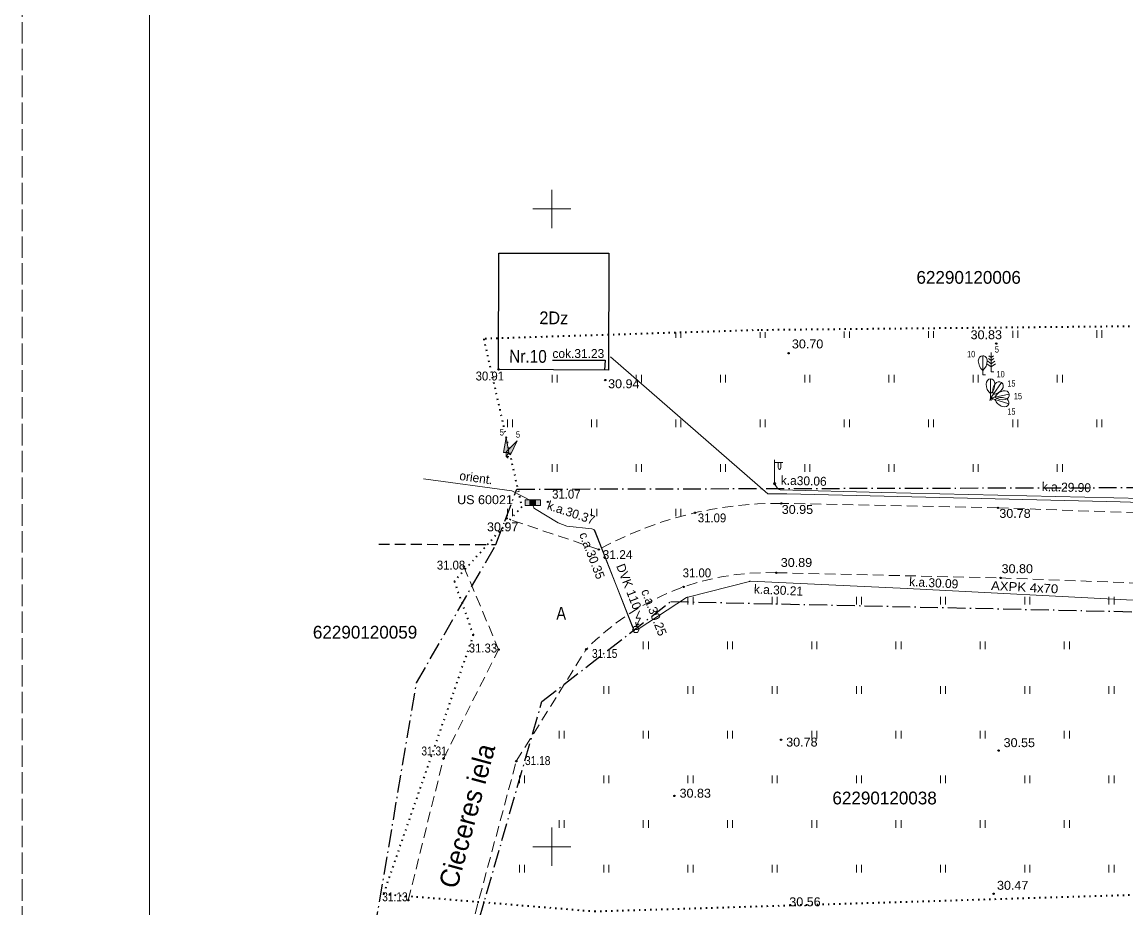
# Model space of a CAD drawing. Extents: x 380758 to 381729, y 283236 to 283533.
# Drawn here: x 380758.5 to 380845, y 283295.2 to 283364.6 of the extents above; entities that cross this region are included whole.
import ezdxf
from ezdxf.enums import TextEntityAlignment as Align

# ---------------------------------------------------------------- set-up
doc = ezdxf.new("R2010")
doc.units = 0
doc.header["$LTSCALE"] = 0.28
for name, pattern in [('DOT_DASHED', [7.7, 5, -1.2, 0.3, -1.2]), ('DOTTED', [1.5, 0.3, -1.2]), ('LONG_DASHED', [7.5, 6, -1.5]), ('MEDIUM_DASHED', [4.5, 3, -1.5])]:
    doc.linetypes.add(name, pattern=pattern)
for name, color, linetype, lineweight in [('1', 7, 'Continuous', 13), ('12', 7, 'Continuous', 13), ('17', 7, 'Continuous', 13), ('18', 7, 'Continuous', 13), ('23', 7, 'Continuous', 13), ('25', 7, 'DOTTED', 35), ('29', 7, 'DOT_DASHED', 25), ('30', 7, 'Continuous', 13), ('37', 7, 'MEDIUM_DASHED', 13), ('4', 7, 'Continuous', 13), ('40', 7, 'Continuous', 25), ('42', 7, 'Continuous', 13), ('44', 7, 'Continuous', 13), ('45', 7, 'Continuous', 13), ('58', 7, 'Continuous', 25), ('63', 7, 'Continuous', 13), ('7', 7, 'Continuous', 13)]:
    doc.layers.add(name, color=color, linetype=linetype, lineweight=lineweight)
for name, color, linetype in [('5', 7, 'Continuous'), ('56', 7, 'Continuous'), ('59', 7, 'Continuous')]:
    doc.layers.add(name, color=color, linetype=linetype)

msp = doc.modelspace()

# ---------------------------------------------------------------- hatches: boundary and pattern name
at = {"layer": '1'}
for points in [[(380796.204, 283330.898), (380796.624, 283330.898), (380796.414, 283332.078)], [(380796.424, 283330.961), (380796.769, 283330.721), (380797.271, 283331.809)]]:
    msp.add_hatch(color=256, dxfattribs=at).paths.add_polyline_path(points)
at = {"layer": '18'}
for points in [[(380797.9, 283327.193), (380799.1, 283327.193), (380799.1, 283326.743), (380797.9, 283326.743)], [(380798.724, 283326.748), (380798.276, 283326.748), (380798.276, 283327.188), (380798.724, 283327.188)]]:
    msp.add_hatch(color=256, dxfattribs=at).paths.add_polyline_path(points)

# ---------------------------------------------------------------- linework, layer by layer
at = {"layer": '1'}
for p, q in [((380834.439, 283338.739), (380834.439, 283337.239)), ((380833.778, 283338.491), (380833.778, 283337.343)), ((380834.439, 283337.613), (380834.107, 283337.857)), ((380834.439, 283337.863), (380834.161, 283338.067)), ((380834.439, 283338.113), (380834.223, 283338.271)), ((380834.439, 283338.363), (380834.263, 283338.491)), ((380834.439, 283338.363), (380834.613, 283338.491)), ((380834.439, 283338.113), (380834.655, 283338.271)), ((380834.439, 283337.863), (380834.717, 283338.067)), ((380834.439, 283337.613), (380834.773, 283337.857)), ((380833.778, 283337.343), (380833.778, 283336.991)), ((380833.778, 283336.991), (380833.978, 283336.991)), ((380834.439, 283337.239), (380834.639, 283337.239)), ((380834.384, 283336.671), (380834.384, 283335.523)), ((380835.251, 283336.395), (380834.587, 283335.458)), ((380834.384, 283335.523), (380834.384, 283335.171)), ((380834.587, 283335.458), (380834.384, 283335.171)), ((380834.728, 283335.245), (380834.384, 283335.171)), ((380835.851, 283335.485), (380834.728, 283335.245)), ((380834.384, 283335.171), (380834.324, 283334.98)), ((380834.384, 283335.171), (380834.584, 283335.171)), ((380834.384, 283335.171), (380834.547, 283335.055)), ((380834.384, 283335.171), (380834.426, 283334.975)), ((380834.72, 283335.065), (380834.384, 283335.171)), ((380835.815, 283334.72), (380834.72, 283335.065)), ((380796.414, 283330.578), (380796.414, 283330.898)), ((380796.414, 283330.578), (380796.597, 283330.841)), ((380796.414, 283330.578), (380796.624, 283330.578)), ((380796.414, 283330.578), (380796.586, 283330.458))]:
    msp.add_line(p, q, dxfattribs=at)
for points in [[(380796.204, 283330.898), (380796.624, 283330.898), (380796.414, 283332.078)], [(380796.424, 283330.961), (380796.769, 283330.721), (380797.271, 283331.809)]]:
    msp.add_lwpolyline(points, close=True, dxfattribs=at)
for centre, major_axis, start_param, end_param in [((380833.778, 283338.091), (0, 0.4), 0, 1.5707963), ((380834.2533, 283338.1144), (0, -0.9434), 4.7372004, 5.6697113), ((380833.778, 283338.091), (0, -0.4), 1.5707963, 3.1415927), ((380833.778, 283338.091), (0, -0.4), 1.5707963, 3.1415927), ((380833.3027, 283338.1144), (0, -0.9434), 0.613474, 1.5459849), ((380834.384, 283336.271), (0, 0.4), 0, 1.5707963), ((380834.8593, 283336.2944), (0, -0.9434), 4.7372004, 5.6697113), ((380834.384, 283336.271), (0, -0.4), 1.5707963, 3.1415927), ((380834.384, 283336.271), (0, -0.4), 1.5707963, 3.1415927), ((380833.9087, 283336.2944), (0, -0.9434), 0.613474, 1.5459849), ((380835.4211, 283335.8132), (-0.5452, -0.77), 4.7372004, 5.6697113), ((380835.0197, 283336.0687), (0.2312, 0.3264), 0, 1.5707963), ((380835.0197, 283336.0687), (0.2312, 0.3264), 4.712389, 6.2831853), ((380835.0197, 283336.0687), (0.2312, 0.3264), 4.712389, 6.2831853), ((380834.6453, 283336.3625), (-0.5452, -0.77), 0.613474, 1.5459849), ((380835.3127, 283334.3802), (-0.8998, 0.2835), 4.7372004, 5.6697113), ((380835.3832, 283335.8707), (-0.9226, -0.1973), 0.613474, 1.5459849), ((380835.582, 283334.9412), (-0.9226, -0.1973), 4.7372004, 5.6697113), ((380835.4597, 283335.401), (0.3912, 0.0836), 0, 1.5707963), ((380835.4597, 283335.401), (0.3912, 0.0836), 4.712389, 6.2831853), ((380835.4597, 283335.401), (0.3912, 0.0836), 4.712389, 6.2831853), ((380835.5983, 283335.2868), (-0.8998, 0.2835), 0.613474, 1.5459849), ((380835.4332, 283334.8405), (0.3815, -0.1202), 4.712389, 6.2831853), ((380835.4332, 283334.8405), (0.3815, -0.1202), 4.712389, 6.2831853), ((380835.4332, 283334.8405), (0.3815, -0.1202), 0, 1.5707963)]:
    msp.add_ellipse(centre, major_axis=major_axis, ratio=0.875, start_param=start_param, end_param=end_param, dxfattribs=at)
at = {"layer": '12'}
msp.add_line((380806.611, 283317.324), (380806.852, 283317.463), dxfattribs=at)
msp.add_lwpolyline([(380806.86, 283318.486), (380806.611, 283317.923), (380806.947, 283317.923), (380806.611, 283317.324), (380806.589, 283317.594)], dxfattribs=at)
msp.add_lwpolyline([(380806.455, 283316.794), (380806.721, 283316.794), (380806.854, 283317.024), (380806.721, 283317.255), (380806.455, 283317.255), (380806.322, 283317.024)], close=True, dxfattribs=at)
at = {"layer": '17'}
msp.add_lwpolyline([(380804.593, 283338.414), (380816.933, 283327.653), (380818.427, 283327.661), (380844.555, 283327.03), (380886.1, 283325.687), (380904.276, 283326.741), (380940.58, 283328.76), (380961.003, 283330.131)], dxfattribs=at)
at = {"layer": '18'}
for points in [[(380797.9, 283327.193), (380799.1, 283327.193), (380799.1, 283326.743), (380797.9, 283326.743)], [(380798.724, 283326.748), (380798.276, 283326.748), (380798.276, 283327.188), (380798.724, 283327.188)]]:
    msp.add_lwpolyline(points, close=True, dxfattribs=at)
at = {"layer": '23'}
for p, q in [((380836.12, 283339.9), (380836.12, 283340.454)), ((380836.52, 283339.9), (380836.52, 283340.456)), ((380842.72, 283339.9), (380842.72, 283340.49)), ((380843.12, 283339.9), (380843.12, 283340.492)), ((380809.72, 283339.9), (380809.72, 283340.308)), ((380810.12, 283339.9), (380810.12, 283340.31)), ((380816.32, 283339.9), (380816.32, 283340.345)), ((380816.72, 283339.9), (380816.72, 283340.347)), ((380822.92, 283339.9), (380822.92, 283340.381)), ((380823.32, 283339.9), (380823.32, 283340.383)), ((380829.52, 283339.9), (380829.52, 283340.417)), ((380829.92, 283339.9), (380829.92, 283340.42)), ((380800.02, 283336.4), (380800.02, 283337)), ((380800.42, 283336.4), (380800.42, 283337)), ((380806.62, 283336.4), (380806.62, 283337)), ((380807.02, 283336.4), (380807.02, 283337)), ((380813.22, 283336.4), (380813.22, 283337)), ((380813.62, 283336.4), (380813.62, 283337)), ((380819.82, 283336.4), (380819.82, 283337)), ((380820.22, 283336.4), (380820.22, 283337)), ((380826.42, 283336.4), (380826.42, 283337)), ((380826.82, 283336.4), (380826.82, 283337)), ((380833.02, 283336.4), (380833.02, 283337)), ((380833.42, 283336.4), (380833.42, 283337)), ((380839.62, 283336.4), (380839.62, 283337)), ((380840.02, 283336.4), (380840.02, 283337)), ((380796.52, 283332.9), (380796.52, 283333.5)), ((380796.92, 283332.9), (380796.92, 283333.5)), ((380803.12, 283332.9), (380803.12, 283333.5)), ((380803.52, 283332.9), (380803.52, 283333.5)), ((380809.72, 283332.9), (380809.72, 283333.5)), ((380810.12, 283332.9), (380810.12, 283333.5)), ((380816.32, 283332.9), (380816.32, 283333.5)), ((380816.72, 283332.9), (380816.72, 283333.5)), ((380822.92, 283332.9), (380822.92, 283333.5)), ((380823.32, 283332.9), (380823.32, 283333.5)), ((380829.52, 283332.9), (380829.52, 283333.5)), ((380829.92, 283332.9), (380829.92, 283333.5)), ((380836.12, 283332.9), (380836.12, 283333.5)), ((380836.52, 283332.9), (380836.52, 283333.5)), ((380842.72, 283332.9), (380842.72, 283333.5)), ((380843.12, 283332.9), (380843.12, 283333.5)), ((380800.02, 283329.4), (380800.02, 283330)), ((380800.42, 283329.4), (380800.42, 283330)), ((380806.62, 283329.4), (380806.62, 283330)), ((380807.02, 283329.4), (380807.02, 283330)), ((380813.22, 283329.4), (380813.22, 283330)), ((380813.62, 283329.4), (380813.62, 283330)), ((380819.82, 283329.4), (380819.82, 283330)), ((380820.22, 283329.4), (380820.22, 283330)), ((380826.42, 283329.4), (380826.42, 283330)), ((380826.82, 283329.4), (380826.82, 283330)), ((380833.02, 283329.4), (380833.02, 283330)), ((380833.42, 283329.4), (380833.42, 283330)), ((380839.62, 283329.4), (380839.62, 283330)), ((380840.02, 283329.4), (380840.02, 283330)), ((380796.52, 283325.9), (380796.52, 283326.5)), ((380796.92, 283325.9), (380796.92, 283326.5)), ((380803.12, 283325.9), (380803.12, 283326.5)), ((380803.52, 283325.9), (380803.52, 283326.5)), ((380809.72, 283325.9), (380809.72, 283326.5)), ((380810.12, 283325.901), (380810.12, 283326.5)), ((380810.668, 283318.984), (380810.668, 283319.584)), ((380811.068, 283318.984), (380811.068, 283319.584)), ((380817.268, 283318.984), (380817.268, 283319.584)), ((380817.668, 283318.984), (380817.668, 283319.584)), ((380823.868, 283318.984), (380823.868, 283319.584)), ((380824.268, 283318.984), (380824.268, 283319.584)), ((380830.468, 283318.984), (380830.468, 283319.584)), ((380830.868, 283318.984), (380830.868, 283319.584)), ((380837.068, 283318.984), (380837.068, 283319.584)), ((380837.468, 283318.984), (380837.468, 283319.584)), ((380843.668, 283318.984), (380843.668, 283319.584)), ((380844.068, 283318.984), (380844.068, 283319.584)), ((380807.168, 283315.484), (380807.168, 283316.084)), ((380807.568, 283315.484), (380807.568, 283316.084)), ((380813.768, 283315.484), (380813.768, 283316.084)), ((380814.168, 283315.484), (380814.168, 283316.084)), ((380820.368, 283315.484), (380820.368, 283316.084)), ((380820.768, 283315.484), (380820.768, 283316.084)), ((380826.968, 283315.484), (380826.968, 283316.084)), ((380827.368, 283315.484), (380827.368, 283316.084)), ((380833.568, 283315.484), (380833.568, 283316.084)), ((380833.968, 283315.484), (380833.968, 283316.084)), ((380840.168, 283315.484), (380840.168, 283316.084)), ((380840.568, 283315.484), (380840.568, 283316.084)), ((380804.068, 283311.984), (380804.068, 283312.584)), ((380804.468, 283311.984), (380804.468, 283312.584)), ((380810.668, 283311.984), (380810.668, 283312.584)), ((380811.068, 283311.984), (380811.068, 283312.584)), ((380817.268, 283311.984), (380817.268, 283312.584)), ((380817.668, 283311.984), (380817.668, 283312.584)), ((380823.868, 283311.984), (380823.868, 283312.584)), ((380824.268, 283311.984), (380824.268, 283312.584)), ((380830.468, 283311.984), (380830.468, 283312.584)), ((380830.868, 283311.984), (380830.868, 283312.584)), ((380837.068, 283311.984), (380837.068, 283312.584)), ((380837.468, 283311.984), (380837.468, 283312.584)), ((380843.668, 283311.984), (380843.668, 283312.584)), ((380844.068, 283311.984), (380844.068, 283312.584)), ((380800.568, 283308.484), (380800.568, 283309.084)), ((380800.968, 283308.484), (380800.968, 283309.084)), ((380807.168, 283308.484), (380807.168, 283309.084)), ((380807.568, 283308.484), (380807.568, 283309.084)), ((380813.768, 283308.484), (380813.768, 283309.084)), ((380814.168, 283308.484), (380814.168, 283309.084)), ((380820.368, 283308.484), (380820.368, 283309.084)), ((380820.768, 283308.484), (380820.768, 283309.084)), ((380826.968, 283308.484), (380826.968, 283309.084)), ((380827.368, 283308.484), (380827.368, 283309.084)), ((380833.568, 283308.484), (380833.568, 283309.084)), ((380833.968, 283308.484), (380833.968, 283309.084)), ((380840.168, 283308.484), (380840.168, 283309.084)), ((380840.568, 283308.484), (380840.568, 283309.084)), ((380797.468, 283304.984), (380797.468, 283305.584)), ((380797.868, 283304.984), (380797.868, 283305.584)), ((380804.068, 283304.984), (380804.068, 283305.584)), ((380804.468, 283304.984), (380804.468, 283305.584)), ((380810.668, 283304.984), (380810.668, 283305.584)), ((380811.068, 283304.984), (380811.068, 283305.584)), ((380817.268, 283304.984), (380817.268, 283305.584)), ((380817.668, 283304.984), (380817.668, 283305.584)), ((380823.868, 283304.984), (380823.868, 283305.584)), ((380824.268, 283304.984), (380824.268, 283305.584)), ((380830.468, 283304.984), (380830.468, 283305.584)), ((380830.868, 283304.984), (380830.868, 283305.584)), ((380837.068, 283304.984), (380837.068, 283305.584)), ((380837.468, 283304.984), (380837.468, 283305.584)), ((380843.668, 283304.984), (380843.668, 283305.584)), ((380844.068, 283304.984), (380844.068, 283305.584)), ((380800.568, 283301.484), (380800.568, 283302.084)), ((380800.968, 283301.484), (380800.968, 283302.084)), ((380807.168, 283301.484), (380807.168, 283302.084)), ((380807.568, 283301.484), (380807.568, 283302.084)), ((380813.768, 283301.484), (380813.768, 283302.084)), ((380814.168, 283301.484), (380814.168, 283302.084)), ((380820.368, 283301.484), (380820.368, 283302.084)), ((380820.768, 283301.484), (380820.768, 283302.084)), ((380826.968, 283301.484), (380826.968, 283302.084)), ((380827.368, 283301.484), (380827.368, 283302.084)), ((380833.568, 283301.484), (380833.568, 283302.084)), ((380833.968, 283301.484), (380833.968, 283302.084)), ((380840.168, 283301.484), (380840.168, 283302.084)), ((380840.568, 283301.484), (380840.568, 283302.084)), ((380797.468, 283297.984), (380797.468, 283298.584)), ((380797.868, 283297.984), (380797.868, 283298.584)), ((380804.068, 283297.984), (380804.068, 283298.584)), ((380804.468, 283297.984), (380804.468, 283298.584)), ((380810.668, 283297.984), (380810.668, 283298.584)), ((380811.068, 283297.984), (380811.068, 283298.584)), ((380817.268, 283297.984), (380817.268, 283298.584)), ((380817.668, 283297.984), (380817.668, 283298.584)), ((380823.868, 283297.984), (380823.868, 283298.584)), ((380824.268, 283297.984), (380824.268, 283298.584)), ((380830.468, 283297.984), (380830.468, 283298.584)), ((380830.868, 283297.984), (380830.868, 283298.584)), ((380837.068, 283297.984), (380837.068, 283298.584)), ((380837.468, 283297.984), (380837.468, 283298.584)), ((380843.668, 283297.984), (380843.668, 283298.584)), ((380844.068, 283297.984), (380844.068, 283298.584))]:
    msp.add_line(p, q, dxfattribs=at)
at = {"layer": '25'}
msp.add_lwpolyline([(381026.117, 283349.86), (380986.913, 283346.195), (380951.371, 283344.43), (380924.511, 283343.073), (380900.74, 283340.36), (380898.299, 283339.817), (380883.648, 283341.174), (380816.227, 283340.496), (380794.658, 283339.817), (380797.642, 283326.649), (380792.352, 283320.811), (380793.844, 283316.603), (380786.796, 283296.295), (380803.346, 283294.938), (380856.387, 283296.567), (380876.057, 283297.653), (380895.999, 283299.961), (380927.606, 283299.553), (380945.042, 283301.724), (380965.254, 283306.611), (380999.033, 283308.647)], dxfattribs=at)
at = {"layer": '29', "linetype": 'MEDIUM_DASHED'}
msp.add_line((380786.44, 283323.725), (380795.614, 283323.68), dxfattribs=at)
at = {"layer": '29'}
msp.add_line((380785.41, 283289.25), (380789.389, 283312.838), dxfattribs=at)
for points in [[(380789.389, 283312.838), (380795.614, 283323.68), (380796.313, 283325.53), (380797.258, 283328.029), (380871.687, 283328.222)], [(380792.473, 283287.96), (380799.228, 283311.375), (380809.317, 283319.223), (380866.546, 283317.96)]]:
    msp.add_lwpolyline(points, dxfattribs=at)
at = {"layer": '30'}
for points in [[(380800, 283351.5), (380800, 283350), (380800, 283348.5)], [(380798.5, 283350), (380800, 283350), (380801.5, 283350)], [(380800, 283301.5), (380800, 283300), (380800, 283298.5)], [(380798.5, 283300), (380800, 283300), (380801.5, 283300)]]:
    msp.add_lwpolyline(points, dxfattribs=at)
at = {"layer": '37'}
for p, q in [((380834.961, 283326.567), (380817.983, 283326.914)), ((380803.683, 283323.296), (380796.455, 283325.739)), ((380793.101, 283321.954), (380795.83, 283315.453))]:
    msp.add_line(p, q, dxfattribs=at)
for points in [[(380834.961, 283326.567), (380851.502, 283325.975), (380864.891, 283325.592), (380886.523, 283325.131), (380905.252, 283325.817), (380927.524, 283327.258), (380929.257, 283330.296), (380935.262, 283331.232), (380936.928, 283327.931), (380958.412, 283329.259), (380975.495, 283330.864), (380976.443, 283332.543)], [(380817.606, 283321.48), (380835.175, 283321.069), (380851.583, 283320.452)], [(380788.746, 283295.803), (380791.513, 283306.929), (380795.83, 283315.453)], [(380793.982, 283294.731), (380797.216, 283306.704), (380802.692, 283315.484)]]:
    msp.add_lwpolyline(points, dxfattribs=at)
for centre, radius, start, end in [((380817.7195, 283297.8864), 29.0287, 89.47988, 118.91669), ((380816.9192, 283301.6422), 19.8497, 88.0173, 135.78674)]:
    msp.add_arc(centre, radius, start, end, dxfattribs=at)
at = {"layer": '40'}
msp.add_lwpolyline([(380804.462, 283346.528), (380804.447, 283337.347), (380795.828, 283337.412), (380795.843, 283346.542)], close=True, dxfattribs=at)
at = {"layer": '42', "lineweight": 25}
msp.add_lwpolyline([(380800.058, 283338.144), (380804.169, 283338.144), (380804.13, 283337.349)], dxfattribs=at)
at = {"layer": '44'}
for p, q in [((380817.461, 283328.452), (380817.461, 283330.335)), ((380817.461, 283330.119), (380818.096, 283330.114)), ((380817.751, 283330.117), (380817.751, 283329.723)), ((380817.961, 283330.115), (380817.961, 283329.723))]:
    msp.add_line(p, q, dxfattribs=at)
msp.add_circle((380817.461, 283328.452), 0.09, dxfattribs=at)
msp.add_ellipse((380817.856, 283329.7225), major_axis=(0, -0.1509), ratio=0.695971, start_param=4.712389, end_param=7.8539816, dxfattribs=at)
at = {"layer": '45'}
msp.add_line((380817.461, 283328.452), (380817.654, 283328.132), dxfattribs=at)
msp.add_lwpolyline([(380817.903, 283327.988), (380825.857, 283327.779), (380846.321, 283327.3), (380868.413, 283326.498)], dxfattribs=at)
msp.add_arc((380817.9109, 283328.2876), 0.3, 211.14658, 268.49702, dxfattribs=at)
at = {"layer": '58'}
for centre in [(380818.554, 283338.6891), (380834.834, 283339.4431), (380795.828, 283337.4121), (380804.187, 283336.5811), (380799.686, 283327.0281), (380817.983, 283326.9141), (380834.961, 283326.5671), (380796.455, 283325.7391), (380811.219, 283326.1781), (380803.683, 283323.2961), (380793.101, 283321.9541), (380817.606, 283321.4801), (380835.175, 283321.0691), (380810.332, 283320.3671), (380795.83, 283315.4531), (380802.692, 283315.4841), (380817.969, 283308.3881), (380835.011, 283307.5421), (380791.513, 283306.9291), (380797.216, 283306.7041), (380809.612, 283303.9801), (380834.626, 283296.3151), (380788.746, 283295.8031)]:
    msp.add_circle(centre, 0.0534, dxfattribs=at)
at = {"layer": '63', "linetype": 'LONG_DASHED'}
msp.add_lwpolyline([(381352.477, 283469.645), (380758.477, 283469.645), (380758.477, 283259.645), (381352.477, 283259.645)], dxfattribs=at)
at = {"layer": '63'}
msp.add_lwpolyline([(381349.977, 283262.145), (380768.477, 283262.145), (380768.477, 283467.145)], dxfattribs=at)
at = {"layer": '7'}
for p, q in [((380798.542, 283326.976), (380798.536, 283326.785)), ((380803.294, 283324.894), (380806.468, 283316.892)), ((380803.389, 283324.729), (380806.312, 283317.211)), ((380810.653, 283319.574), (380815.487, 283320.8)), ((380806.755, 283317.068), (380810.564, 283319.535))]:
    msp.add_line(p, q, dxfattribs=at)
for points in [[(380798.491, 283327.059), (380796.868, 283327.888), (380789.937, 283328.83)], [(380798.643, 283326.518), (380800.501, 283325.382), (380801.168, 283325.14), (380803.143, 283324.918)], [(380815.574, 283320.809), (380827.86, 283320.238), (380846.055, 283319.297), (380859.988, 283318.493), (380866.245, 283318.786), (380868.63, 283318.749)]]:
    msp.add_lwpolyline(points, dxfattribs=at)
for centre, radius, start, end in [((380798.9619, 283326.8018), 0.4265, 182.1906, 221.71061), ((380803.1092, 283324.6201), 0.3, 21.25188, 83.5927), ((380815.5606, 283320.5093), 0.3, 87.33926, 104.23043), ((380810.7266, 283319.2833), 0.3, 104.23043, 122.93322), ((380806.5921, 283317.3201), 0.3, 201.25188, 302.93322)]:
    msp.add_arc(centre, radius, start, end, dxfattribs=at)

# ---------------------------------------------------------------- texts
at = {"layer": '1'}
for s, width, p in [('10', 0.75, (380832.548, 283338.37)), ('5', 0.85, (380834.719, 283338.739)), ('10', 0.75, (380834.856, 283336.795)), ('15', 0.75, (380835.701, 283336.07)), ('15', 0.75, (380836.214, 283335.073)), ('15', 0.75, (380835.701, 283333.864)), ('5', 0.85, (380795.915, 283332.237)), ('5', 0.85, (380797.184, 283332.071))]:
    msp.add_text(s, height=0.5, dxfattribs=dict(at, width=width)).set_placement(p)
at = {"layer": '37', "width": 0.85}
msp.add_text('A', height=1, dxfattribs=at).set_placement((380800.7335, 283317.804), align=Align.CENTER)
at = {"layer": '4', "width": 0.95}
msp.add_text('2Dz', height=1, rotation=359.568, dxfattribs=at).set_placement((380799.019, 283340.966))
at = {"layer": '42'}
msp.add_text('cok.31.23', height=0.7, dxfattribs=at).set_placement((380800.048, 283338.312))
at = {"layer": '45'}
for s, p in [('k.a30.06', (380817.941, 283328.383)), ('k.a.29.90', (380838.4, 283327.886))]:
    msp.add_text(s, height=0.7, rotation=358.497, dxfattribs=at).set_placement(p)
at = {"layer": '5', "width": 0.9}
msp.add_text('Nr.10', height=1, rotation=359.568, dxfattribs=at).set_placement((380796.657, 283337.956))
at = {"layer": '56'}
msp.add_text('Cieceres iela', height=1.5, rotation=74.885, dxfattribs=at).set_placement((380792.564, 283296.629))
at = {"layer": '58'}
for s, width, p in [('30.83', 1.05, (380832.822, 283339.784)), ('30.70', 1.05, (380818.816, 283339.064)), ('30.91', 0.95, (380794.028, 283336.549)), ('30.94', 1.05, (380804.411, 283335.943)), ('31.07', 0.95, (380800.023, 283327.29)), ('30.95', 1.05, (380818.02, 283326.088)), ('31.09', 0.95, (380811.443, 283325.427)), ('30.78', 1.05, (380835.073, 283325.779)), ('30.97', 1.05, (380794.918, 283324.726)), ('31.08', 0.95, (380790.985, 283321.727)), ('30.89', 1.05, (380817.943, 283321.93)), ('31.00', 0.95, (380810.257, 283321.117)), ('30.80', 1.05, (380835.249, 283321.444)), ('31.33', 0.95, (380793.487, 283315.226)), ('31.15', 0.85, (380803.145, 283314.803)), ('30.78', 1.05, (380818.368, 283307.854)), ('30.55', 1.05, (380835.41, 283307.808)), ('31.31', 0.85, (380789.775, 283307.155)), ('31.18', 0.85, (380797.896, 283306.401)), ('30.83', 1.05, (380810.011, 283303.846)), ('30.47', 1.05, (380834.892, 283296.626)), ('31.13', 0.85, (380786.705, 283295.727)), ('30.56', 1.05, (380818.612, 283295.332))]:
    msp.add_text(s, height=0.7, dxfattribs=dict(at, width=width)).set_placement(p)
msp.add_text('31.24', height=0.7, dxfattribs=at).set_placement((380803.982, 283322.545))
at = {"layer": '59'}
for s, p in [('62290120006', (380828.579, 283344.133)), ('62290120059', (380781.27, 283316.316)), ('62290120038', (380821.991, 283303.32))]:
    msp.add_text(s, height=1, dxfattribs=at).set_placement(p)
at = {"layer": '7'}
for s, rotation, p in [('orient.', 352.261, (380794.0099, 283328.5796)), ('DVK 110', 291.246, (380805.7103, 283320.2693))]:
    msp.add_text(s, height=0.7, rotation=rotation, dxfattribs=at).set_placement(p, align=Align.CENTER)
at = {"layer": '7', "width": 1.05}
msp.add_text('US 60021', height=0.7, dxfattribs=at).set_placement((380792.576, 283326.854))
at = {"layer": '7'}
for s, rotation, p in [('k.a.30.37', 341.574, (380799.578, 283326.47)), ('c.a.30.35', 291.252, (380802.128, 283324.491)), ('k.a.30.21', 357.339, (380815.825, 283319.856)), ('k.a.30.09', 357.039, (380827.992, 283320.438)), ('c.a.30.25', 291.252, (380806.984, 283320.041))]:
    msp.add_text(s, height=0.7, rotation=rotation, dxfattribs=at).set_placement(p)
at = {"layer": '7', "width": 1.1}
msp.add_text('AXPK 4x70', height=0.7, rotation=357.039, dxfattribs=at).set_placement((380837.0414, 283319.9941), align=Align.CENTER)

doc.saveas('drawing.dxf')
